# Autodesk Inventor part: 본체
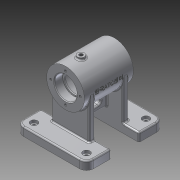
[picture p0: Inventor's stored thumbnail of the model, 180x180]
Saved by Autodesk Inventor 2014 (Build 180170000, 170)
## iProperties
Created: 2016-07
Part Number: 본체
Material: 알루미늄 6061
Document SubType Name: Modeling
Designer: basic
Density: 2.71 g/cm^3
Appearance: 알루미늄 - 평지
Mass: 547.948 g
Surface Area: 574.579 cm^2
Volume: 202.195 cm^3
Author: basic
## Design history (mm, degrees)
sketch "스케치1"
  geometry: L1 (35, 70)-(-35, 70); L2 (35, 70)-(35, 97); L3 (35, 97)-(-35, 97); L4 (-35, 97)-(-35, 70); 2 further points
  constraints: 8 end point, 1 horizontal, 1 midpoint, 1 parallel, 1 perpendicular, 1 vertical, 1 vertical alignment
  dimensions: "d0" = 70 distance of L1.start L1.end; "d1" = 70 distance from line of L1 point (0, 0); "d2" = 54 diameter of L3 L1
revolve "회전1" sketch "스케치1" stored, may be unused: angle "d3" = 90 deg
sketch "스케치2"
  geometry: L1 (-49, 0)-(49, 0) reference; L2 (35, 43)-(35, 97) reference; L3 (-35, 43)-(-35, 97) reference; L4 (35, 70)-(-35, 70); L5 (35, 70)-(35, 86); L6 (35, 86)-(23, 86); L7 (23, 86)-(23, 84); L8 (23, 84)-(21, 84); L9 (21, 84)-(21, 92); L10 (21, 92)-(-21, 92); L11 (-21, 92)-(-21, 84); L12 (-21, 84)-(-23, 84); L13 (-23, 84)-(-23, 86); L14 (-23, 86)-(-35, 86); L15 (-35, 70)-(-35, 86); 5 further points
  constraints: 24 end point, 6 midpoint, 6 parallel, 3 collinear, 3 perpendicular, 2 horizontal alignment, 2 point on line
  dimensions: "d4" = 32 diameter of L6 L4; "d5" = 28 diameter of L8 L4; "d6" = 44 diameter of L10 L4; "d7" = 42 distance of L9.end L10.end; "d8" = 12 distance of L5.end L6.end
revolve "회전2" sketch "스케치2" stored, may be unused: angle "d9" = 90 deg
sketch "스케치3"
  geometry: L1 (-20, -50)-(-55, -50); L2 (-55, -50)-(-55, 50); L3 (-55, 50)-(-20, 50); L4 (-20, 50)-(-20, -50); L5 (-20, -50)-(-55, 50); L6 (-55, -50)-(-20, 50); L7 (55, -50)-(20, -50); L8 (20, -50)-(20, 50); L9 (20, 50)-(55, 50); L10 (55, 50)-(55, -50); L11 (55, -50)-(20, 50); L12 (20, -50)-(55, 50); 8 further points
  constraints: 24 end point, 9 midpoint, 4 parallel, 3 horizontal alignment, 2 horizontal, 2 perpendicular, 1 collinear
  dimensions: "d10" = 100 distance of L1.end L2.end; "d11" = 110 distance between parallel lines of L10 L2; "d12" = 35 distance of L1.start L1.end; "d13" = 55 distance from line of L2 point (0, 0)
extrude "돌출1" join sketch "스케치3" distance "d14" = 12; taper "d15" = 0 deg
sketch "스케치4"
  geometry: L1 (-20, -50)-(-20, 50) reference; L2 (-20, -27)-(-28, -27); L3 (-28, -27)-(-28, 27); L4 (-28, 27)-(-20, 27); L5 (-20, 27)-(-20, -27); L6 (-20, -27)-(-28, 27); L7 (-28, -27)-(-20, 27); 3 further points
  constraints: 12 end point, 4 midpoint, 2 parallel, 1 horizontal, 1 perpendicular
  dimensions: "d16" = 8 distance of L2.start L2.end; "d17" = 54 distance of L2.end L3.end
extrude "돌출2" join sketch "스케치4" stored distance "d18" = 12; taper "d19" = 0 deg
node "작업 평면1"
sketch "스케치6"
  geometry: L1 (24.368, -4)-(-24.368, -4); L2 (-24.368, -4)-(-24.368, 4); L3 (-24.368, 4)-(24.368, 4); L4 (24.368, 4)-(24.368, -4); L5 (24.368, -4)-(-24.368, 4); L6 (-24.368, -4)-(24.368, 4); L7 (-20, 50)-(-20, -50) reference; L8 (20, -50)-(20, 50) reference; 7 further points; 1 other entity
  constraints: 12 end point, 5 midpoint, 2 parallel, 1 coincident, 1 horizontal, 1 perpendicular, 2 other
  dimensions: "d24" = 8 distance of L3.end L1.start
extrude "돌출4" join sketch "스케치6" stored distance "d25" = 8; taper "d26" = 0 deg
sketch "스케치7"
  geometry: L1 (0, 21.298)-(40, 21.298) reference; L2 (0, 0)-(0, 21.298) reference; L3 (12, 10.649)-(28, 10.649); L4 (12, 7.149)-(28, 7.149); L5 (28, 14.149)-(12, 14.149); A1 r 3.5 centre (12, 10.649) between (12, 14.149) and (12, 7.149); A2 r 3.5 centre (28, 10.649) between (28, 7.149) and (28, 14.149); 4 further points
  constraints: 8 end point, 4 point on circle, 4 tangent, 3 midpoint, 2 centre point, 2 parallel, 1 horizontal alignment, 1 vertical alignment
  dimensions: "d27" = 3.5 radius of A2; "d170" = 23 dimension on A1 A2
extrude "돌출5" cut sketch "스케치7" stored distance "d29" = 8; taper "d30" = 0 deg
node "작업 평면2"
sketch "스케치8"
  geometry: L1 (-35, 27)-(-35, -27) reference; C1 r 5 at (-13, 0); 1 further point
  constraints: 1 centre point, 1 horizontal alignment
  dimensions: "d32" = 22 distance from line of L1 C1.centre; "d33" = 10 diameter of C1
extrude "돌출6" join sketch "스케치8" stored distance "d34" = 8; taper "d35" = 0 deg
sketch "스케치9" dims "d46" = 42
  geometry: C1 r 16 at (0, 0) reference; C2 r 27 at (0, 0) reference; 3 further points
  constraints: 2 horizontal alignment, 1 coincident, 2 other
hole "구멍2" sketch "스케치9" at (-21, 0) diameter "d47" = 3.242; stored, may be unused: countersink angle "d51" = 90 deg, drill point angle "d53" = 118 deg; dims "d48" = 8, "d49" = 4, "d50" = 2, "d52" = 10
sketch "스케치10"
  geometry: L1 (0, 70)-(0, 43); L2 (0, 70)-(15.898, 44.559); L3 (15.898, 44.559)-(20.986, 47.738); L4 (20.986, 47.738)-(16.747, 54.522); L5 (16.747, 54.522)-(11.658, 51.343); C1 r 22 at (0, 70) reference; 1 further point
  constraints: 10 end point, 3 perpendicular, 1 point on line, 1 tangent, 1 vertical, 1 vertical alignment, 1 other
  dimensions: "d59" = 32 deg angle of L1 L2; "d60" = 30 distance of L1.start L2.end; "d62" = 12 diameter of L4 L2
revolve "회전3" sketch "스케치10" stored, may be unused: angle "d63" = 90 deg
sketch "스케치12"
  geometry: L1 (-42.5, 37.5)-(-42.5, -37.5); L2 (-55, -50)-(-55, 50) reference; 2 further points
  constraints: 2 end point, 1 horizontal alignment, 1 midpoint, 1 vertical
  dimensions: "d91" = 75 distance of L1.start L1.end; "d93" = 12.5 distance between parallel lines of L2 L1
hole "구멍4" sketch "스케치12" at (-42.5, -37.5), (-42.5, 37.5) diameter "d94" = 6; stored, may be unused: countersink angle "d98" = 90 deg, drill point angle "d100" = 0 deg; dims "d95" = 8, "d96" = 10, "d97" = 4, "d99" = 10
fillet "모깎기4" dims "d102" = 2
fillet "모깎기5" dims "d103" = 2
fillet "모깎기7" dims "d105" = 2
fillet "모깎기9" dims "d107" = 2
fillet "모깎기11" dims "d109" = 2
fillet "모깎기13" dims "d111" = 0.3
fillet "모깎기14" dims "d112" = 3
chamfer "모따기1" distance "d113" = 1; stored, may be unused: second distance "d114" = 2, angle "d115" = 45 deg
node "작업 평면3"
sketch "스케치13"
  geometry: L1 (35, 97)-(-35, 97) reference; L2 (-35, 97)-(-35, 43) reference; 2 further points
  constraints: 1 other
  dimensions: "d117" = 35 distance from line of L2 point (0, 70); "d118" = 27 distance from line of L1 point (0, 70)
feature "엠보싱1" sketch "스케치13" dims "d0" = 70, "d1" = 70, "d2" = 54, "d4" = 32, "d5" = 28, "d6" = 44, "d7" = 42, "d8" = 12, "d119" = 0.5, "d120" = 0
hole "구멍5" diameter "d144" = 5.188; stored, may be unused: countersink angle "d148" = 90 deg, drill point angle "d150" = 0 deg; dims "d142" = 10, "d143" = 10, "d145" = 8, "d146" = 10, "d147" = 4, "d149" = 10
hole "구멍6" diameter "d153" = 5.188; stored, may be unused: countersink angle "d157" = 90 deg, drill point angle "d159" = 0 deg; dims "d151" = 10, "d152" = 10, "d154" = 8, "d155" = 10, "d156" = 4, "d158" = 10
fillet "모깎기22" dims "d160" = 2
fillet "모깎기23" dims "d161" = 2
fillet "모깎기24" dims "d168" = 10
fillet "모깎기25" dims "d169" = 2
node "솔리드1"
mirror "대칭1"
pattern_circular "원형 패턴1" dims angle "d55" = 360 deg
mirror "대칭2"
mirror "대칭3"
node "투영된 루프1"
other parameters: "d23" = 22, "d116" = -27
